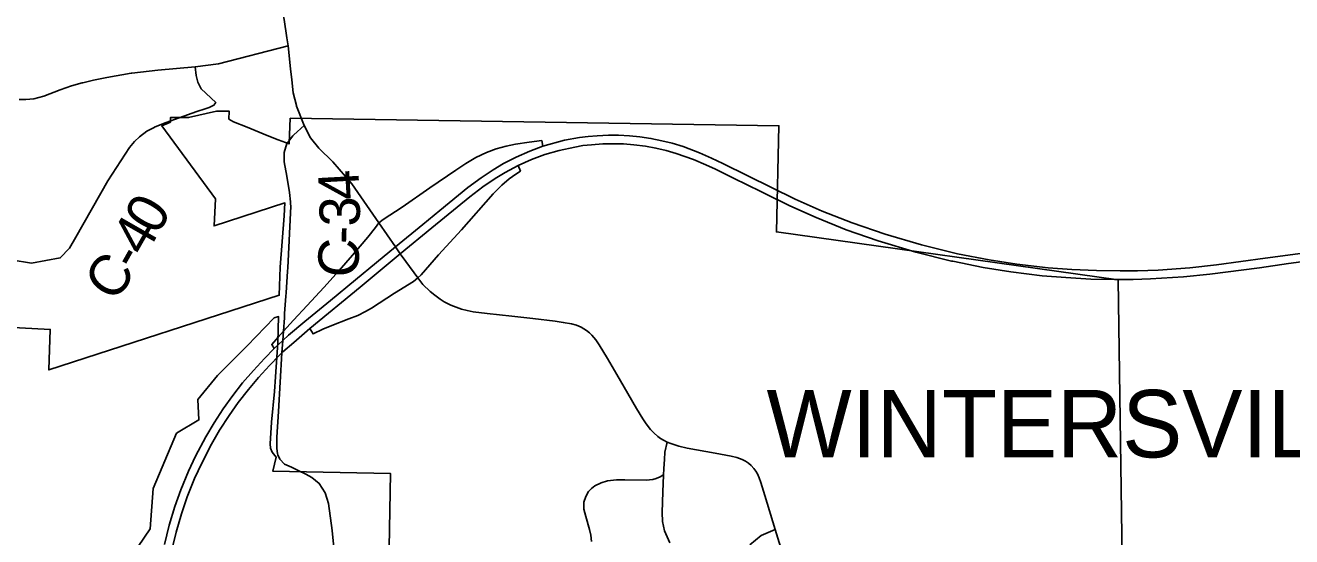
# Model space of a CAD drawing. Extents: x 2402298 to 2498138, y 789485 to 950881.
# Drawn here: x 2459820 to 2469210, y 873839 to 877630 of the extents above; entities that cross this region are included whole.
import ezdxf

# ---------------------------------------------------------------- set-up
doc = ezdxf.new("R2010")
doc.units = 0
for name, color, linetype in [('GM_X_City_Street', 7, 'Continuous'), ('GM_X_Corporation', 7, 'Continuous'), ('GM_X_Corporation_Text', 7, 'Continuous'), ('GM_X_County_Road', 7, 'Continuous'), ('GM_X_County_Road_Text', 7, 'Continuous'), ('GM_X_Interchange_Ramps', 7, 'Continuous'), ('GM_X_State_Route', 7, 'Continuous'), ('GM_X_US_Route', 7, 'Continuous'), ('SH_Text', 7, 'Continuous')]:
    doc.layers.add(name, color=color, linetype=linetype)

msp = doc.modelspace()

# ---------------------------------------------------------------- linework, layer by layer
at = {"layer": 'GM_X_City_Street'}
for points in [[(2464598.3, 873793.9), (2464559.8, 873883.8), (2464545.3, 873951.7), (2464541.5, 874018.9), (2464547.7, 874172.3), (2464552.1, 874295), (2464554.1, 874343.8), (2464558.2, 874411.7), (2464562.2, 874465.1), (2464578, 874539.2)], [(2464547.7, 874294.3), (2464526.1, 874282), (2464496.3, 874270.4), (2464471.9, 874263.6), (2464422.4, 874257.6), (2464266.2, 874261.4), (2464203.3, 874260.7), (2464136.7, 874252.8), (2464089.4, 874238.3), (2464041.8, 874215.2), (2464018.5, 874196.9), (2463995.6, 874173), (2463976.5, 874136.1), (2463961.5, 874095), (2463960.2, 874068.6), (2463961.8, 874043.3), (2463976.3, 873987.9), (2464002.6, 873891.5), (2464012.8, 873850.3), (2464016.7, 873803.3)], [(2465191.1, 873779.1), (2465275.3, 873848.5), (2465379.7, 873892.8)]]:
    msp.add_lwpolyline(points, dxfattribs=at)
at = {"layer": 'GM_X_Corporation'}
for points in [[(2459091.5, 875424.2), (2460004.3, 875375.9), (2459993.7, 875075.4), (2461702.1, 875629.3), (2461708.7, 875836.3), (2461739.8, 876218.4), (2461745.2, 876313), (2461219, 876142.4), (2461229.5, 876342.3), (2460831.9, 876884), (2460895.4, 876912.9), (2460895.5, 876945.5), (2461029.8, 876945.4), (2461238.1, 876992.3), (2461331.5, 876992.3), (2461329.3, 876934.4), (2461364.5, 876915.3), (2461465.6, 876875.2), (2461613.1, 876812.1), (2461693.9, 876781.6), (2461775.9, 876750.8), (2461776.3, 876755.9), (2461784.5, 876940.5), (2465407.2, 876885.7), (2465389.3, 876098.1), (2467923.7, 875742.8), (2467958.1, 873334.8)], [(2462511.5, 873484.8), (2462527.1, 874308.5), (2461656, 874324.4), (2461679.9, 874429.6), (2461649.5, 874466.8), (2461637.9, 874495.3), (2461634.5, 874527.1), (2461644.1, 874687.5), (2461668.6, 874916.2), (2461675.3, 875024.8), (2461691.1, 875279.1), (2461697.2, 875470.9), (2461664.1, 875461.4), (2461463.8, 875254.3), (2461244.2, 875035), (2461098.7, 874855.5), (2461106.5, 874704.8), (2460941.5, 874605.9), (2460835, 874355.5), (2460767.4, 874196.3), (2460746.4, 873897.9), (2460563.5, 873627.2)]]:
    msp.add_lwpolyline(points, dxfattribs=at)
at = {"layer": 'GM_X_County_Road'}
for p, q in [((2461811.5, 876818), (2461886.6, 876888.2)), ((2461753.6, 875647.9), (2461764.9, 875806.6))]:
    msp.add_line(p, q, dxfattribs=at)
for points in [[(2461154.1, 877011), (2461183.3, 877020.6), (2461218.2, 877036.7), (2461231.7, 877056.4), (2461123.8, 877159.1), (2461099.9, 877207.9), (2461086.4, 877258.8), (2461078.6, 877322.2)], [(2460961.4, 876944.3), (2461091, 876990.2), (2461154.1, 877011)], [(2460769, 876870.7), (2460782, 876877.4), (2460865.3, 876910.4), (2460961.4, 876944.3)], [(2459300.2, 875782.7), (2459330.1, 875802.6), (2459407.9, 875831.9), (2459714, 875891.6), (2459865.6, 875867.3), (2460078.8, 875905.1), (2460148.3, 875978.1), (2460193.4, 876059.7), (2460432.2, 876476.3), (2460592.7, 876722.9), (2460629.2, 876768.9), (2460667.4, 876803.6), (2460721.2, 876846.1), (2460769, 876870.7)], [(2461785.4, 876322.2), (2461779.8, 876391.1), (2461759, 876512.5), (2461739.3, 876617.4), (2461740.3, 876686.9), (2461760, 876754.2), (2461775.6, 876774.4), (2461778.8, 876778.4)], [(2461778.8, 876778.4), (2461803.8, 876810.7), (2461807.7, 876814.4), (2461811.5, 876818)], [(2461764.9, 875806.6), (2461766.8, 875833.1), (2461788.1, 876290.4), (2461786.7, 876306.3), (2461785.4, 876322.2)], [(2461742.6, 875493.5), (2461751.7, 875621.5), (2461753.6, 875647.9)], [(2461696.9, 874767.7), (2461722, 875202.1), (2461728.3, 875292.6), (2461733.2, 875362.2), (2461740.4, 875462.7), (2461742.6, 875493.5)], [(2461685.1, 874508.9), (2461685.9, 874576.4), (2461696.9, 874767.7)], [(2461792.9, 874353.9), (2461741.5, 874378), (2461707.4, 874413.4), (2461691.8, 874446.1), (2461690.3, 874456.6), (2461684.9, 874493.3), (2461685.1, 874508.9)], [(2462117.9, 873657.5), (2462095.2, 873885), (2462066.8, 874085.7), (2462042.9, 874165.3), (2461999.7, 874234.7), (2461943.7, 874277.1), (2461900.6, 874301.6), (2461848.9, 874327.6), (2461792.9, 874353.9)]]:
    msp.add_lwpolyline(points, dxfattribs=at)
at = {"layer": 'GM_X_Interchange_Ramps'}
for points in [[(2463657.5, 876733.7), (2463648.5, 876775.3), (2463556.1, 876763.2), (2463455.6, 876748.5), (2463384.3, 876734.3), (2463311.4, 876714.2), (2463239, 876687.6), (2463160.2, 876650.9), (2463085.2, 876605.6), (2463012.8, 876555), (2462820.2, 876425), (2462612.9, 876281.8), (2462473.4, 876190.5), (2462440.4, 876164.8)], [(2462729.8, 875757.5), (2462754.1, 875779.1), (2462884.6, 875927.7), (2463053, 876114.5), (2463289.8, 876380.8), (2463353.7, 876443.7), (2463408.4, 876490.6), (2463457.5, 876526.6), (2463491.4, 876549.3), (2463473.6, 876589.8)], [(2462440.4, 876164.8), (2462417.5, 876131.7), (2462360.2, 876059.6), (2462246.5, 875925.6), (2462146.5, 875811.7), (2462032.1, 875685.7), (2461910.1, 875553.1), (2461809.4, 875443.2), (2461733.2, 875362.2), (2461693.6, 875317.1)], [(2461929.1, 875382.1), (2461953.5, 875342), (2462026.4, 875377.6), (2462091.3, 875404), (2462219.1, 875452.9), (2462286.4, 875479.7), (2462343.1, 875507.5), (2462385.7, 875533), (2462556.3, 875643.1), (2462697.8, 875730.5), (2462729.8, 875757.5)], [(2461693.6, 875317.1), (2461646.7, 875263.7), (2461666.1, 875234.8)]]:
    msp.add_lwpolyline(points, dxfattribs=at)
at = {"layer": 'GM_X_State_Route'}
for points in [[(2461769.4, 877478.8), (2461759, 877537), (2461740.3, 877672.9), (2461708.6, 877810.4), (2461365, 879301.4), (2461296.4, 879505.1), (2461209.1, 879664.4), (2461129.9, 879804.4), (2461047.2, 879934.2), (2460924.3, 880129.2), (2460921.5, 880133.6)], [(2460605, 877274.9), (2460610.1, 877275.8), (2460801.8, 877296.3), (2461078.6, 877322.2), (2461253.4, 877345.2), (2461769.4, 877478.8)], [(2461831.4, 877030.9), (2461829.6, 877035.6), (2461806.7, 877130.1), (2461796.4, 877224.5), (2461786, 877307.6), (2461769.4, 877478.8)], [(2459775, 877080.5), (2459824.5, 877079.6), (2459882.7, 877084), (2459958.2, 877103.9), (2460078.7, 877151.4), (2460161.3, 877180.3), (2460240.3, 877202.9), (2460245.4, 877204)], [(2460245.4, 877204), (2460326.2, 877222), (2460425.2, 877241.9), (2460605, 877274.9)], [(2462440.4, 876164.8), (2462239.7, 876453.7), (2462100.4, 876618.1), (2461996.7, 876718), (2461933.4, 876796.9), (2461886.6, 876888.2), (2461831.4, 877030.9)], [(2462641.6, 875879.1), (2462600.4, 875935.9), (2462564.8, 875986.7), (2462440.4, 876164.8)], [(2462926.4, 875580.8), (2462894.8, 875599.8), (2462855.6, 875628.8), (2462821.9, 875656.3), (2462767.9, 875708.1), (2462729.8, 875757.5), (2462641.6, 875879.1)], [(2465503.1, 873491.8), (2465379.7, 873892.8), (2465304, 874144.9), (2465273.6, 874241.8), (2465260.9, 874276.5), (2465248.1, 874304.6), (2465236.7, 874325.1), (2465222.8, 874343.8), (2465201.7, 874366.6), (2465182.4, 874383.3), (2465159.8, 874398.9), (2465134.5, 874411.7), (2465095.2, 874425.7), (2465053.2, 874435.8), (2464934.1, 874458.1), (2464728.1, 874496.1), (2464666.6, 874510.1), (2464605.1, 874528.8), (2464578, 874539.2), (2464551, 874554.3), (2464530.3, 874567), (2464509, 874582.7), (2464479.3, 874608.6), (2464454.5, 874634.7), (2464423.9, 874674.8), (2464399.3, 874712.1), (2464351.9, 874789.9), (2464288.1, 874901.5), (2464205.7, 875042.4), (2464136.5, 875160.5), (2464075.4, 875261.6), (2464050.1, 875297.8), (2464020.4, 875333), (2464002.6, 875350.3), (2463980.7, 875367.3), (2463961.6, 875381.1), (2463940.7, 875392.1), (2463905.7, 875406.2), (2463869.4, 875417.2), (2463808.8, 875427.9), (2463748.4, 875436), (2463584, 875455.6), (2463428.2, 875472.7), (2463245.3, 875492.8), (2463139.4, 875507.1), (2463095.8, 875516), (2463054.1, 875526.8), (2463014.5, 875539.4), (2462973.9, 875554.9), (2462935.4, 875575.4), (2462926.4, 875580.8)]]:
    msp.add_lwpolyline(points, dxfattribs=at)
at = {"layer": 'GM_X_US_Route'}
for points in [[(2461666.1, 875234.8), (2461728.3, 875292.6), (2461771.9, 875332.3), (2461893, 875433.7), (2462082.2, 875589.4), (2462268.7, 875742.2), (2462423.4, 875870.6), (2462564.8, 875986.7), (2462766.9, 876153.2), (2462893.7, 876258), (2463101.6, 876426.8), (2463198.7, 876499.9), (2463288.1, 876559.4), (2463365.3, 876604.6), (2463458.5, 876653), (2463559.9, 876696.7), (2463657.5, 876733.7)], [(2462584.1, 875922.3), (2462600.4, 875935.9), (2462835.2, 876127.8), (2463116.1, 876357.8), (2463213.2, 876431.7), (2463302.7, 876493.4), (2463378.3, 876538.9), (2463473.6, 876589.8), (2463573.4, 876634.4), (2463670.9, 876671.4), (2463779.2, 876703), (2463894.5, 876727.6), (2463954, 876737.8), (2464018.3, 876744.3), (2464103, 876750.2), (2464174.8, 876751.8), (2464255.5, 876750.2), (2464332.4, 876744.3), (2464417.1, 876733), (2464495.1, 876719.1), (2464572.3, 876701.1), (2464646, 876680.5), (2464773.1, 876635.4), (2464864.5, 876596.3), (2464938.4, 876562.5), (2465104.9, 876480.6)], [(2463657.5, 876733.7), (2463817.7, 876777.3), (2463929.8, 876797.2), (2463993.2, 876805.5), (2464058.9, 876811.3), (2464145.1, 876814.8), (2464217.8, 876815.1), (2464298.6, 876810.9), (2464377.4, 876802.9), (2464458.7, 876791.1), (2464538.8, 876774.1), (2464615.7, 876755.8), (2464696.5, 876730.5), (2464817.9, 876684.1), (2464906.6, 876645.9), (2464992.2, 876606.5), (2465177.7, 876514.3), (2465528.1, 876341.6), (2465727.7, 876252.9), (2465950.1, 876165.1), (2466194.5, 876080.5), (2466465.2, 876002), (2466731.8, 875937), (2466966.6, 875890.8), (2467170.7, 875859.8), (2467403.3, 875832.5), (2467580.4, 875818.7), (2467762.1, 875811.1), (2467938.6, 875809.1), (2468066.4, 875809.8), (2468219.9, 875815.2), (2468453.8, 875832.5), (2468651.8, 875854), (2469011.9, 875903), (2469328.7, 875946.6)], [(2465104.9, 876480.6), (2465138.1, 876464.2), (2465477.7, 876296.9), (2465487.5, 876292.5)], [(2465487.5, 876292.5), (2465683, 876204.2), (2465905, 876114.7), (2466142.4, 876031), (2466421.7, 875947.9), (2466687.6, 875882.5), (2466698.1, 875880.4)], [(2461730, 875209.1), (2461810.6, 875279.8), (2461929.1, 875382.1), (2462303.5, 875689.3), (2462584.1, 875922.3)], [(2466698.1, 875880.4), (2466922.9, 875834.8), (2467127.7, 875802.1), (2467359.3, 875773.7), (2467535.6, 875759.3), (2467719.5, 875749.1), (2467895.9, 875745.3), (2468022.1, 875745.8)], [(2468022.1, 875745.8), (2468033.1, 875745.9), (2468163.4, 875750.7), (2468407.8, 875764.6), (2468604, 875784.4), (2468970.1, 875833.2), (2469185.4, 875863)], [(2469185.4, 875863), (2469280, 875876.1)], [(2460850.9, 873781.7), (2460886.1, 873924.2), (2460928.4, 874063), (2460972.9, 874187.6), (2461029.6, 874325), (2461081.9, 874436.5), (2461157.8, 874578.7), (2461220.3, 874683.5), (2461287.9, 874787.6), (2461359.3, 874886), (2461431.1, 874978.9), (2461510.8, 875072.1), (2461592.9, 875160.5), (2461666.1, 875234.8)], [(2460904.4, 873731.7), (2460938.1, 873872.7), (2460978.3, 874009.4), (2461020.7, 874134.3), (2461074.8, 874271), (2461127.9, 874384.6), (2461199.7, 874525.1), (2461260.8, 874629), (2461332.1, 874738.4), (2461398.1, 874832.7), (2461474.2, 874929.8), (2461548.7, 875020.4), (2461629.6, 875107.7), (2461701.7, 875181.7), (2461722, 875202.1), (2461730, 875209.1)]]:
    msp.add_lwpolyline(points, dxfattribs=at)
at = {"layer": 'SH_Text'}
msp.add_line((2462641.6, 875879.1), (2462729.8, 875757.5), dxfattribs=at)
for points in [[(2460921.5, 880133.6), (2460924.3, 880129.2), (2461047.2, 879934.2), (2461129.9, 879804.4), (2461209.1, 879664.4), (2461296.4, 879505.1), (2461365, 879301.4), (2461708.6, 877810.4), (2461740.3, 877672.9), (2461759, 877537), (2461769.4, 877478.8)], [(2461769.4, 877478.8), (2461786, 877307.6), (2461796.4, 877224.5), (2461806.7, 877130.1), (2461829.6, 877035.6), (2461831.4, 877030.9)], [(2461831.4, 877030.9), (2461886.6, 876888.2), (2461933.4, 876796.9), (2461996.7, 876718), (2462100.4, 876618.1), (2462239.7, 876453.7), (2462440.4, 876164.8)], [(2463657.5, 876733.7), (2463648.5, 876775.3), (2463556.1, 876763.2), (2463455.6, 876748.5), (2463384.3, 876734.3), (2463311.4, 876714.2), (2463239, 876687.6), (2463160.2, 876650.9), (2463085.2, 876605.6), (2463012.8, 876555), (2462820.2, 876425), (2462612.9, 876281.8), (2462473.4, 876190.5), (2462440.4, 876164.8)], [(2463473.6, 876589.8), (2463573.4, 876634.4), (2463670.9, 876671.4), (2463779.2, 876703), (2463894.5, 876727.6), (2463954, 876737.8), (2464018.3, 876744.3), (2464103, 876750.2), (2464174.8, 876751.8), (2464255.5, 876750.2), (2464332.4, 876744.3), (2464417.1, 876733), (2464495.1, 876719.1), (2464572.3, 876701.1), (2464646, 876680.5), (2464773.1, 876635.4), (2464864.5, 876596.3), (2464938.4, 876562.5), (2465104.9, 876480.6)], [(2469328.7, 875946.6), (2469011.9, 875903), (2468651.8, 875854), (2468453.8, 875832.5), (2468219.9, 875815.2), (2468066.4, 875809.8), (2467938.6, 875809.1), (2467762.1, 875811.1), (2467580.4, 875818.7), (2467403.3, 875832.5), (2467170.7, 875859.8), (2466966.6, 875890.8), (2466731.8, 875937), (2466465.2, 876002), (2466194.5, 876080.5), (2465950.1, 876165.1), (2465727.7, 876252.9), (2465528.1, 876341.6), (2465177.7, 876514.3), (2464992.2, 876606.5), (2464906.6, 876645.9), (2464817.9, 876684.1), (2464696.5, 876730.5), (2464615.7, 876755.8), (2464538.8, 876774.1), (2464458.7, 876791.1), (2464377.4, 876802.9), (2464298.6, 876810.9), (2464217.8, 876815.1), (2464145.1, 876814.8), (2464058.9, 876811.3), (2463993.2, 876805.5), (2463929.8, 876797.2), (2463817.7, 876777.3), (2463657.5, 876733.7)], [(2462729.8, 875757.5), (2462754.1, 875779.1), (2462884.6, 875927.7), (2463053, 876114.5), (2463289.8, 876380.8), (2463353.7, 876443.7), (2463408.4, 876490.6), (2463457.5, 876526.6), (2463491.4, 876549.3), (2463473.6, 876589.8)], [(2465104.9, 876480.6), (2465138.1, 876464.2), (2465477.7, 876296.9), (2465487.5, 876292.5)], [(2465487.5, 876292.5), (2465683, 876204.2), (2465905, 876114.7), (2466142.4, 876031), (2466421.7, 875947.9), (2466687.6, 875882.5), (2466698.1, 875880.4)], [(2462440.4, 876164.8), (2462564.8, 875986.7), (2462600.4, 875935.9), (2462641.6, 875879.1)], [(2466698.1, 875880.4), (2466922.9, 875834.8), (2467127.7, 875802.1), (2467359.3, 875773.7), (2467535.6, 875759.3), (2467719.5, 875749.1), (2467895.9, 875745.3), (2468022.1, 875745.8)], [(2468022.1, 875745.8), (2468033.1, 875745.9), (2468163.4, 875750.7), (2468407.8, 875764.6), (2468604, 875784.4), (2468970.1, 875833.2), (2469185.4, 875863)], [(2469185.4, 875863), (2469280, 875876.1)]]:
    msp.add_lwpolyline(points, dxfattribs=at)

# ---------------------------------------------------------------- texts
at = {"layer": 'GM_X_Corporation_Text'}
msp.add_text('WINTERSVILLE', height=500, rotation=0.00001, dxfattribs=at).set_placement((2465315.9, 874426.9))
at = {"layer": 'GM_X_County_Road_Text'}
for s, rotation, p in [('4', 93.1496, (2462300.8, 876341.8)), ('0', 59.68774, (2460797.3, 876065.8)), ('3', 89.82577, (2462300.8, 876138)), ('4', 60.2635, (2460706, 875906)), ('-', 88.18208, (2462296.7, 876005.5)), ('C', 87.59894, (2462286.2, 875756)), ('C', 53.43687, (2460476.7, 875566.8)), ('-', 60.60351, (2460645.7, 875799.1))]:
    msp.add_text(s, height=300, rotation=rotation, dxfattribs=at).set_placement(p)

doc.saveas('drawing.dxf')
